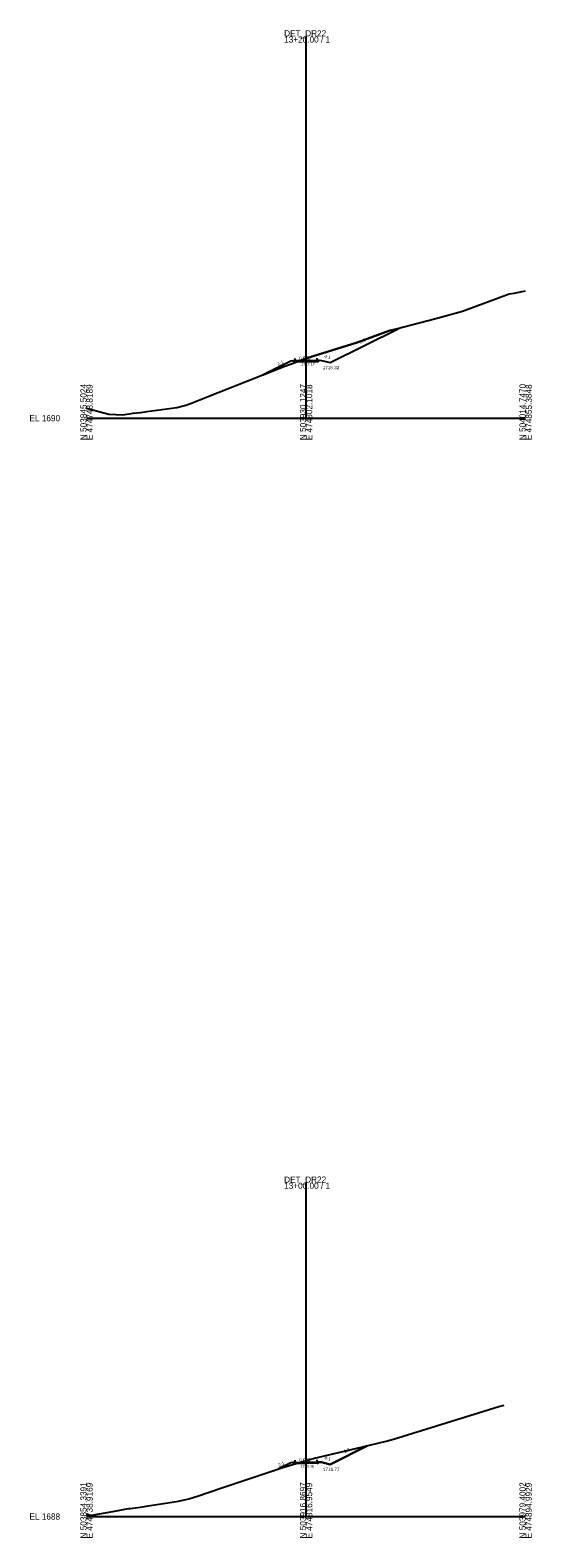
# Model space of a CAD drawing. Extents: x -26 to 1203, y -10 to 9633.
# Drawn here: x -26 to 203, y 7490 to 8177 of the extents above; entities that cross this region are included whole.
import ezdxf

# ---------------------------------------------------------------- set-up
doc = ezdxf.new("R2010")
doc.units = 0
for name, color, linetype in [('Exist Cross Section Cell', 7, 'Continuous'), ('Exist XS Center Line Elevation Label', 7, 'Continuous'), ('Exist XS Ground Line', 7, 'Continuous'), ('Prop XS Ditch Slope Text', 7, 'Continuous'), ('Prop XS Ditch Standard Text', 7, 'Continuous'), ('Prop XS Earthwork Shape', 7, 'Continuous'), ('Prop XS EOT Tick Mark', 7, 'Continuous'), ('Prop XS Finish Grade', 7, 'Continuous'), ('Prop XS Finish Grade Earthwork', 7, 'Continuous'), ('Prop XS Finish Grade Pavement', 7, 'Continuous'), ('Prop XS Pvmt Edge Slope', 7, 'Continuous'), ('Prop XS SE Text', 7, 'Continuous'), ('Prop XS Shoulder Borrow Shape', 7, 'Continuous'), ('Prop XS Side Slope Text', 7, 'Continuous'), ('Prop XS Subgrade Earthwork', 7, 'Continuous')]:
    doc.layers.add(name, color=color, linetype=linetype)

msp = doc.modelspace()

# ---------------------------------------------------------------- linework, layer by layer
at = {"layer": 'Exist Cross Section Cell'}
for p, q in [((100, 8000), (100, 8173.81)), ((0, 8000), (100, 8000)), ((100, 8000), (200, 8000)), ((100, 7500), (100, 7652)), ((0, 7500), (100, 7500)), ((100, 7500), (200, 7500))]:
    msp.add_line(p, q, dxfattribs=at)
at = {"layer": 'Exist XS Ground Line'}
for points in [[(0, 8004.57), (10.15, 8001.9), (16.57, 8001.48), (21.26, 8002.25), (24.65, 8002.66), (27.49, 8003.05), (41.14, 8004.84), (45.22, 8005.91), (47.78, 8006.8), (52.6, 8008.82), (87.63, 8022.59), (90.36, 8023.67), (92.41, 8024.47), (100, 8027.17), (100.31, 8027.29), (123.23, 8034.5), (138.21, 8039.86), (158.49, 8045.21), (171.28, 8048.7), (192.46, 8056.55), (194.76, 8056.93), (200, 8057.94)], [(0, 7500.86), (1.58, 7500.67), (3.39, 7500.73), (13.58, 7502.58), (18.21, 7503.45), (19.19, 7503.61), (19.98, 7503.69), (25.51, 7504.47), (27.2, 7504.74), (41.96, 7506.99), (46.66, 7508.07), (48.54, 7508.62), (50.95, 7509.49), (61.21, 7512.88), (89.38, 7522.36), (100, 7525.45), (103.17, 7526.37), (128.94, 7532.43), (136.5, 7534.31), (139.85, 7535.27), (187.76, 7550.04), (190.21, 7550.67)]]:
    msp.add_lwpolyline(points, dxfattribs=at)
at = {"layer": 'Prop XS Earthwork Shape'}
for points in [[(111, 8025.32), (142.19, 8040.91), (138.21, 8039.86), (123.23, 8034.5), (100.31, 8027.29), (100, 8027.17), (95.79, 8025.67), (100, 8025.76), (105, 8025.86), (105.53, 8025.87), (106.02, 8026.36), (107, 8026.32)], [(93, 8026.04), (80.49, 8019.78), (87.63, 8022.59), (90.36, 8023.67), (92.41, 8024.47), (95.79, 8025.67), (95, 8025.66), (94.45, 8025.64), (93.98, 8026.11)], [(95.43, 7524.12), (100, 7525.45), (103.17, 7526.37), (127.75, 7532.15), (111, 7523.77), (107, 7524.77), (106.02, 7524.81), (105.53, 7524.32), (105, 7524.31), (100, 7524.21)], [(87.42, 7521.71), (89.38, 7522.36), (95.43, 7524.12), (95, 7524.11), (94.45, 7524.1), (93.98, 7524.57), (93, 7524.49)]]:
    msp.add_lwpolyline(points, close=True, dxfattribs=at)
at = {"layer": 'Prop XS EOT Tick Mark'}
for p, q in [((95, 8026.2), (95, 8027.2)), ((105, 8026.4), (105, 8027.4)), ((95, 7524.65), (95, 7525.65)), ((105, 7524.85), (105, 7525.85))]:
    msp.add_line(p, q, dxfattribs=at)
at = {"layer": 'Prop XS Finish Grade'}
for p, q in [((95, 8026.2), (93.98, 8026.11)), ((105, 8026.4), (106.02, 8026.36)), ((95, 7524.65), (93.98, 7524.57)), ((105, 7524.85), (106.02, 7524.81))]:
    msp.add_line(p, q, dxfattribs=at)
at = {"layer": 'Prop XS Finish Grade Earthwork'}
for p, q in [((111, 8025.32), (142.19, 8040.91)), ((93, 8026.04), (80.49, 8019.78)), ((93.98, 8026.11), (93, 8026.04)), ((106.02, 8026.36), (107, 8026.32)), ((107, 8026.32), (111, 8025.32)), ((111, 7523.77), (127.75, 7532.15)), ((93, 7524.49), (87.42, 7521.71)), ((93.98, 7524.57), (93, 7524.49)), ((106.02, 7524.81), (107, 7524.77)), ((107, 7524.77), (111, 7523.77))]:
    msp.add_line(p, q, dxfattribs=at)
at = {"layer": 'Prop XS Finish Grade Pavement'}
for p, q in [((95, 8026.2), (100, 8026.3)), ((100, 8026.3), (105, 8026.4)), ((95, 7524.65), (100, 7524.75)), ((100, 7524.75), (105, 7524.85))]:
    msp.add_line(p, q, dxfattribs=at)
at = {"layer": 'Prop XS Pvmt Edge Slope'}
for p, q in [((95, 8026.2), (94.45, 8025.64)), ((105, 8026.4), (105.53, 8025.87)), ((95, 7524.65), (94.45, 7524.1)), ((105, 7524.85), (105.53, 7524.32))]:
    msp.add_line(p, q, dxfattribs=at)
at = {"layer": 'Prop XS Shoulder Borrow Shape'}
for points in [[(95, 8026.2), (93.98, 8026.11), (94.45, 8025.64)], [(105, 8026.4), (106.02, 8026.36), (105.53, 8025.87)], [(95, 7524.65), (94.45, 7524.1), (93.98, 7524.57)], [(105.53, 7524.32), (106.02, 7524.81), (105, 7524.85)]]:
    msp.add_lwpolyline(points, close=True, dxfattribs=at)
at = {"layer": 'Prop XS Subgrade Earthwork'}
for p, q in [((94.45, 8025.64), (93.98, 8026.11)), ((95, 8025.66), (94.45, 8025.64)), ((100, 8025.76), (95, 8025.66)), ((105, 8025.86), (100, 8025.76)), ((105, 8025.86), (105.53, 8025.87)), ((105.53, 8025.87), (106.02, 8026.36)), ((94.45, 7524.1), (93.98, 7524.57)), ((95, 7524.11), (94.45, 7524.1)), ((100, 7524.21), (95, 7524.11)), ((105, 7524.31), (100, 7524.21)), ((105, 7524.31), (105.53, 7524.32)), ((105.53, 7524.32), (106.02, 7524.81))]:
    msp.add_line(p, q, dxfattribs=at)

# ---------------------------------------------------------------- texts
at = {"layer": 'Exist Cross Section Cell'}
for s, p in [('DET_DR22', (90, 8173.81)), ('13+20.00 / 1', (90, 8171.01)), ('EL 1690', (-26, 7998.6)), ('DET_DR22', (90, 7652)), ('13+00.00 / 1', (90, 7649.2)), ('EL 1688', (-26, 7498.6))]:
    msp.add_text(s, height=2.8, dxfattribs=at).set_placement(p)
for s, p in [('N 503845.5024', (0, 7990)), ('E 474748.8189', (2.8, 7990)), ('N 503930.1247', (100, 7990)), ('E 474802.1018', (102.8, 7990)), ('N 504014.7470', (200, 7990)), ('E 474855.3848', (202.8, 7990)), ('N 503854.3391', (0, 7490)), ('E 474738.9169', (2.8, 7490)), ('N 503916.8697', (100, 7490)), ('E 474816.9549', (102.8, 7490)), ('N 503979.4002', (200, 7490)), ('E 474894.9929', (202.8, 7490))]:
    msp.add_text(s, height=2.8, rotation=90, dxfattribs=at).set_placement(p)
at = {"layer": 'Exist XS Center Line Elevation Label'}
for s, p in [('1717.17', (97.76, 8023.92)), ('1713.45', (97.34, 7522.2))]:
    msp.add_text(s, height=1.25, dxfattribs=at).set_placement(p)
at = {"layer": 'Prop XS Ditch Slope Text'}
for p in [(108.21, 8027.56), (108.21, 7526.02)]:
    msp.add_text('4:1', height=1.5, rotation=345.96376, dxfattribs=at).set_placement(p)
at = {"layer": 'Prop XS Ditch Standard Text'}
for s, p in [('1715.32', (107.61, 8022.32)), ('1711.77', (107.72, 7520.77))]:
    msp.add_text(s, height=1.5, dxfattribs=at).set_placement(p)
at = {"layer": 'Prop XS SE Text'}
for p in [(96.85, 8026.56), (96.85, 7525.01)]:
    msp.add_text('0.020', height=1.5, rotation=1.14576, dxfattribs=at).set_placement(p)
at = {"layer": 'Prop XS Side Slope Text'}
for p in [(124.86, 8033.92), (87.34, 8023.87), (117.64, 7528.77), (87.8, 7522.61)]:
    msp.add_text('2:1', height=1.5, rotation=26.56505, dxfattribs=at).set_placement(p)

doc.saveas('drawing.dxf')
